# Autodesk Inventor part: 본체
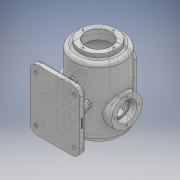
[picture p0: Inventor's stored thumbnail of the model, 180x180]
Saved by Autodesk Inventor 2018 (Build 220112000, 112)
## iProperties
Created: 2021-11
Part Number: 본체
Material: Generic
Document SubType Name: Modeling
Designer: 1class 3
Density: 1 g/cm^3
Appearance: Default
Author: 1class 3
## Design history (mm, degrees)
sketch "스케치1"
  geometry: 1 further point
sketch "스케치2"
  geometry: L1 (65, 80)-(-65, 80); L2 (-65, 80)-(-65, -80); L3 (-65, -80)-(65, -80); L4 (65, -80)-(65, 80); L5 (65, 80)-(-65, -80); L6 (-65, 80)-(65, -80); 1 further point
  constraints: 12 end point, 2 midpoint, 2 parallel, 1 horizontal, 1 perpendicular
  dimensions: "d0" = 130 distance of L3.end L2.end; "d1" = 160 distance of L2.end L1.end
extrude "돌출1" new body sketch "스케치2" distance "d2" = 14; taper "d3" = 0 deg
sketch "스케치3"
  geometry: L1 (-50, 0)-(-24.522, 70); L2 (-50, 0)-(-91.976, 0); L3 (-24.522, 70)-(0, 70); L4 (0, 70)-(0, 0); L5 (0, 0)-(-50, 0); 1 further point
  constraints: 10 end point, 3 horizontal, 2 coincident, 1 perpendicular
  dimensions: "d6" = 110 deg angle of L1 L2; "d8" = 50 distance of L4.end L1.start; "d9" = 70 distance of L3.end L4.end
extrude "돌출2" join sketch "스케치3" stored distance "d10" = 14; taper "d11" = 0 deg
sketch "스케치4"
  geometry: L1 (0, 0)-(70, 0); L2 (0, 60)-(0, 0); L3 (0, 60)-(0, 88.498); L4 (0, 60)-(70, 34.522); L5 (70, 34.522)-(70, 0); L6 (0, -7)-(0, 7) reference; 1 further point
  constraints: 10 end point, 2 vertical, 1 horizontal, 1 midpoint, 1 vertical alignment
  dimensions: "d12" = 60 distance of L2.start L1.start; "d13" = 110 deg angle of L4 L3; "d14" = 70 distance of L1.start L1.end
extrude "돌출3" join sketch "스케치4" stored distance "d15" = 14; taper "d17" = 0 deg; dims "d16" = 7, "d18" = 0
sketch "스케치5"
  geometry: L1 (-14, 80)-(-14, -80) reference; L2 (100, -105)-(100, 105); L3 (70, 7)-(70, -7) reference; L4 (100, 90)-(165, 90); L5 (165, 90)-(165, -80.993); L6 (100, 90)-(100, -105); A1 r 100 centre (100, -5) between (100, -105) and (165, -80.993); 3 further points
  constraints: 8 end point, 2 midpoint, 2 point on circle, 1 centre point, 1 collinear, 1 horizontal, 1 horizontal alignment, 1 perpendicular, 1 point on line, 1 vertical, 1 vertical alignment
  dimensions: "d29" = 114 distance between parallel lines of L1 L2; "d30" = 100 radius of A1; "d31" = 195 distance of L2.start L4.start; "d32" = 65 distance of L4.start L4.end; "d33" = 210 distance of L2.start L2.end
revolve "회전1" sketch "스케치5" stored, may be unused: angle "d34" = 90 deg
feature "쉘1" dims "d35" = 10
sketch "스케치6"
  geometry: C1 r 65 at (0, 0); 1 further point
  constraints: 1 centre point
  dimensions: "d36" = 130 diameter of C1
extrude "돌출4" join sketch "스케치6" distance "d37" = 5; taper "d38" = 0 deg
sketch "스케치7"
  geometry: C1 r 47.5 at (0, 0); 1 further point
  constraints: 1 centre point
  dimensions: "d39" = 95 diameter of C1
extrude "돌출5" join sketch "스케치7" distance "d40" = 10; taper "d41" = 0 deg
sketch "스케치8"
  geometry: C1 r 32.5 at (0, 0); 1 further point
  constraints: 1 centre point
  dimensions: "d42" = 65 diameter of C1
extrude "돌출6" cut sketch "스케치8" stored distance "d43" = 10; taper "d44" = 0 deg
node "작업 평면1"
sketch "스케치9"
  geometry: L1 (-30, -65)-(30, -65); L2 (30, -65)-(30, 55); L3 (30, 55)-(-30, 55); L4 (-30, 55)-(-30, -65); L5 (-30, -65)-(30, 55); L6 (30, -65)-(-30, 55); L7 (47.5, 105)-(-47.5, 105) reference; 3 further points
  constraints: 12 end point, 3 midpoint, 2 parallel, 1 horizontal, 1 perpendicular, 1 vertical alignment
  dimensions: "d46" = 60 distance of L2.end L3.end; "d47" = 120 distance of L1.end L2.end; "d48" = 50 distance between parallel lines of L7 L3
extrude "돌출7" join sketch "스케치9" stored distance "d49" = 10; taper "d50" = 0 deg
node "작업 평면2"
sketch "스케치10"
  geometry: L1 (-14, -80)-(-14, 80) reference; L2 (147.5, 105)-(52.5, 105) reference; C1 r 40 at (100, -22); 1 further point
  constraints: 1 centre point
  dimensions: "d52" = 80 diameter of C1; "d53" = 114 distance from line of C1.centre L1; "d54" = 127 distance from line of L2 C1.centre
extrude "돌출8" join sketch "스케치10" stored distance "d55" = 10; taper "d56" = 0 deg
sketch "스케치11"
  geometry: C1 r 21 at (0, 0); 1 further point
  constraints: 1 centre point
  dimensions: "d57" = 42 diameter of C1
extrude "돌출9" cut sketch "스케치11" extent not by distance; stored distance "d58" = 10; taper "d59" = 0 deg
sketch "스케치12"
  geometry: C1 r 26 at (0, 0); 1 further point
  constraints: 1 centre point
  dimensions: "d60" = 52 diameter of C1
extrude "돌출10" cut sketch "스케치12" distance "d61" = 18; taper "d62" = 0 deg
fillet "모깎기1" dims "d63" = 0.3
sketch "스케치13"
  geometry: A1 r 32.5 centre (0, 0) between (0, 32.5) and (-32.5, 0); 3 further points
  constraints: 4 point on circle, 1 centre point
  dimensions: "d64" = 65 diameter of A1
hole "구멍1" sketch "스케치13" at (0, 32.5), (-32.5, 0), (32.5, 0), (0, -32.5) diameter "d65" = 3.242; stored, may be unused: countersink angle "d69" = 90 deg, drill point angle "d71" = 118 deg; dims "d66" = 8, "d67" = 4, "d68" = 2, "d70" = 13
fillet "모깎기2" dims "d72" = 15
fillet "모깎기3" dims "d73" = 3
sketch "스케치14"
  geometry: L1 (20, 55)-(-20, 55); L2 (-20, 55)-(-20, -45); L3 (-20, -45)-(20, -45); L4 (20, -45)-(20, 55); L5 (20, 55)-(-20, -45); L6 (-20, 55)-(20, -45); L7 (30, 50)-(30, -40) reference; L8 (-15, 65)-(15, 65) reference; 2 further points
  constraints: 12 end point, 2 midpoint, 2 parallel, 1 horizontal, 1 perpendicular
  dimensions: "d74" = 40 distance of L3.end L2.end; "d75" = 100 distance of L2.end L1.end; "d76" = 10 distance between parallel lines of L7 L4; "d77" = 10 distance between parallel lines of L8 L1
extrude "돌출11" cut sketch "스케치14" stored distance "d78" = 18; taper "d79" = 0 deg
fillet "모깎기4" dims "d80" = 5
sketch "스케치15"
  geometry: L1 (-25, 60)-(25, 60); L2 (25, 60)-(25, -50); L3 (25, -50)-(-25, -50); L4 (-25, -50)-(-25, 60); L5 (-25, 60)-(25, -50); L6 (25, 60)-(-25, -50); L7 (30, 50)-(30, -40) reference; L8 (15, -55)-(-15, -55) reference; 6 further points
  constraints: 12 end point, 6 midpoint, 2 parallel, 1 horizontal, 1 perpendicular
  dimensions: "d81" = 50 distance of L2.end L3.end; "d82" = 110 distance of L1.end L2.end; "d83" = 5 distance between parallel lines of L7 L2; "d84" = 5 distance between parallel lines of L8 L3
hole "구멍2" sketch "스케치15" at (25, 5), (-25, 5), (0, 60), (0, -50) diameter "d85" = 3.242; stored, may be unused: countersink angle "d89" = 90 deg, drill point angle "d91" = 118 deg; dims "d86" = 9, "d87" = 4, "d88" = 2, "d90" = 11
fillet "모깎기5" dims "d92" = 10
fillet "모깎기6" dims "d93" = 10
fillet "모깎기7" dims "d94" = 3
fillet "모깎기8" dims "d95" = 20
fillet "모깎기9" dims "d96" = 3
fillet "모깎기10" dims "d97" = 3
fillet "모깎기11" dims "d98" = 3
chamfer "모따기1" distance "d99" = 1; stored, may be unused: second distance "d100" = 2, angle "d101" = 45 deg
sketch "스케치16"
  geometry: A1 r 40 centre (0, 0) between (0, 40) and (-40, 0); 3 further points
  constraints: 4 point on circle, 1 centre point
  dimensions: "d102" = 80 diameter of A1
hole "구멍3" sketch "스케치16" at (0, 40), (-40, 0), (0, -40), (40, 0) diameter "d103" = 3.242; stored, may be unused: countersink angle "d107" = 90 deg, drill point angle "d109" = 118 deg; dims "d104" = 11, "d105" = 4, "d106" = 2, "d108" = 13
sketch "스케치17"
  geometry: L1 (-50, -60)-(50, -60); L2 (50, -60)-(50, 60); L3 (50, 60)-(-50, 60); L4 (-50, 60)-(-50, -60); L5 (-50, -60)-(50, 60); L6 (50, -60)-(-50, 60); 5 further points
  constraints: 12 end point, 4 coincident, 2 midpoint, 2 parallel, 1 horizontal, 1 perpendicular
  dimensions: "d110" = 100 distance of L2.end L3.end; "d111" = 120 distance of L3.end L1.start
hole "구멍4" sketch "스케치17" at (-50, 60), (50, 60), (50, -60), (-50, -60) diameter "d112" = 9; stored, may be unused: countersink angle "d116" = 90 deg, drill point angle "d118" = 0 deg; dims "d113" = 11, "d114" = 18, "d115" = 2, "d117" = 14
sketch "스케치18"
  geometry: L1 (120, 14)-(0, 14) reference; L2 (47.806, 6.794)-(72.051, 6.794); L3 (72.051, 6.794)-(72.051, 3.363); L4 (72.051, 3.363)-(47.806, 3.363); L5 (47.806, 3.363)-(47.806, 6.794); 3 further points
  constraints: 1 midpoint, 1 vertical alignment, 2 other
  dimensions: "d119" = 9 distance from line of L1 point (60, 5)
feature "엠보싱1" sketch "스케치18" dims "d12" = 60, "d13" = 110 deg, "d14" = 70, "d120" = 0.5, "d121" = 0
node "솔리드1"
mirror "미러1"
mirror "미러2"
mirror "미러3"
mirror "미러4"
mirror "미러5"
other parameters: "d45" = -184, "d51" = 75
